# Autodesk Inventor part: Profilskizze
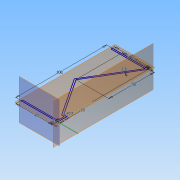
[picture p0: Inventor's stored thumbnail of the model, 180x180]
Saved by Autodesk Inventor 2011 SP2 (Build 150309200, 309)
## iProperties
Created: 2009-11
Part Number: Profilskizze
Document SubType Name: Modeling
Designer: gkramp
Density: 1 g/cm^3
d0: 100,000 mm
d1: 40,000 mm
d2: 50,000 mm
d3: 30,000 mm
d4: 3,477 mm
d5: 10,000 mm
d6: 40,000 mm
d7: 1,500 mm
Author: gkramp
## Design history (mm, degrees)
sketch "Skizze1"
  geometry: L1 (-40, 100)-(0, 100); L2 (0, 100)-(-30, 50); L3 (-30, 50)-(-3.477, 10); L4 (-3.477, 10)-(0, 10); L5 (0, 10)-(0, 0); L6 (0, 0)-(-40, 0); L7 (0, 37.459)-(0, -9.286) reference; L8 (-3.707, 0)-(22.509, 0) reference; L9 (-40, 98.5)-(-2.649, 98.5); L10 (-2.649, 98.5)-(-31.773, 49.96); L11 (-31.773, 49.96)-(-4.283, 8.5); L12 (-4.283, 8.5)-(-1.5, 8.5); L13 (-1.5, 8.5)-(-1.5, 1.5); L14 (-1.5, 1.5)-(-40, 1.5); L15 (-40, 100)-(-40, 98.5); L16 (-40, 1.5)-(-40, 0)
  constraints: 28 end point, 6 perpendicular, 4 parallel, 1 horizontal, 5 other
  dimensions: "d0" = 100 distance between parallel lines of L6 L1; "d1" = 40 distance of L1.start L1.end; "d2" = 50 distance from line of L2.end L1; "d3" = 30 horizontal distance of L1.end L2.end; "d4" = 3.4774 distance of L3.end L4.end; "d5" = 10 distance of L4.end L5.end; "d6" = 40 distance of L5.end L6.end; "d7" = 1.5 distance between parallel lines of L10 L2; "d9" = 0 distance between parallel lines of L6 L8; "d10" = 0 distance between parallel lines of L7 L5; "d11" = 0 distance from line of L7 L1.end
node "Volumenkörpern"
node "Oberflächenkörpern"
